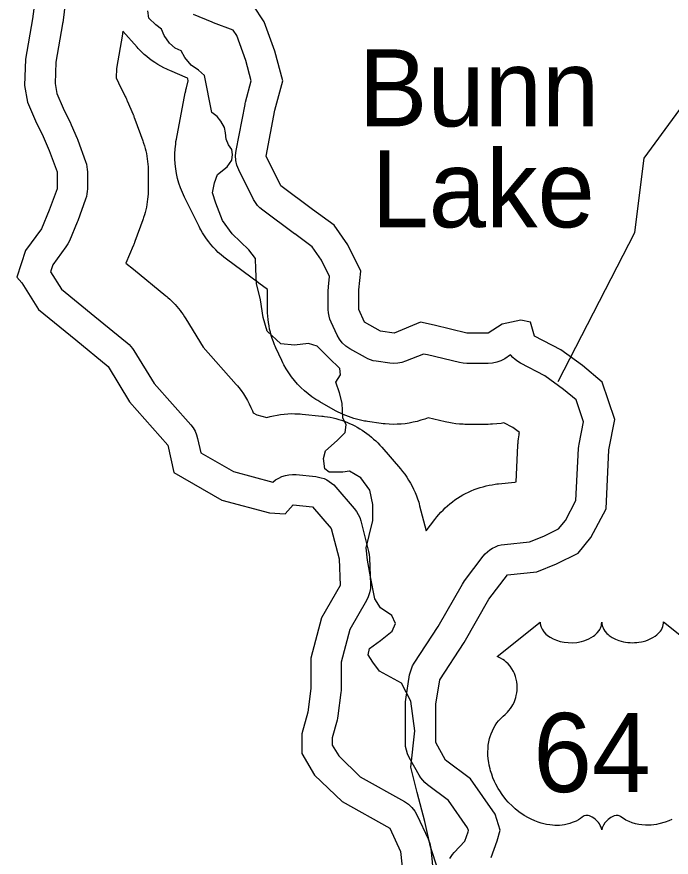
# Model space of a CAD drawing. Extents: x 2126262 to 2293712, y 749403 to 919119.
# Drawn here: x 2213752 to 2215366, y 768873 to 770944 of the extents above; entities that cross this region are included whole.
import ezdxf

# ---------------------------------------------------------------- set-up
doc = ezdxf.new("R2010")
doc.units = 0
for name, color, linetype in [('Exist Boundary Political CountyLine', 7, 'Continuous'), ('Exist Hydrographic Buffer Line', 7, 'Continuous'), ('Exist Hydrographic Lake Shore', 7, 'Continuous'), ('Exist Hydrographic Lake Shore Label', 7, 'Continuous'), ('Exist Hydrographic Misc Water Feature', 7, 'Continuous'), ('Exist Road Primary US Shield CELL', 7, 'Continuous'), ('Exist Road Primary US Shield Number Label', 7, 'Continuous')]:
    doc.layers.add(name, color=color, linetype=linetype)

msp = doc.modelspace()

# ---------------------------------------------------------------- linework, layer by layer
at = {"layer": 'Exist Boundary Political CountyLine'}
msp.add_lwpolyline([(2214790.3, 768843.6), (2214772, 768898.4), (2214757.8, 768961.4), (2214739.5, 769032.4), (2214723.3, 769095.3), (2214733.5, 769184.7), (2214723.3, 769257.8), (2214701, 769302.4), (2214646.2, 769331.9), (2214629.9, 769354.2), (2214618.7, 769372), (2214621.8, 769387.2), (2214649.2, 769407.5), (2214677.6, 769429.8), (2214685.7, 769449.1), (2214676.6, 769468.4), (2214649.2, 769487.7), (2214635, 769510), (2214623.8, 769563.8), (2214616.7, 769605.4), (2214613.7, 769635.9), (2214620.8, 769666.3), (2214629.9, 769702.9), (2214629.9, 769742.5), (2214622.8, 769777.5), (2214600.5, 769807.9), (2214572.1, 769824.2), (2214555.8, 769822.1), (2214522.3, 769822.1), (2214511.2, 769830.3), (2214508.1, 769855.6), (2214513.2, 769874.9), (2214541.6, 769900.3), (2214561.9, 769919.6), (2214563.9, 769938.9), (2214555.8, 769956.1), (2214554.5, 769992), (2214547.5, 770017.1), (2214538.9, 770044), (2214550.1, 770062.2), (2214548.4, 770077.8), (2214521.5, 770103.8), (2214509.4, 770115.9), (2214492.9, 770132.4), (2214471.3, 770139.3), (2214436.6, 770135), (2214402.8, 770138.4), (2214369, 770169.6), (2214359.5, 770203.4), (2214352.5, 770246.8), (2214343, 770286.7), (2214341.3, 770322.2), (2214340.4, 770348.2), (2214323.9, 770369.9), (2214283.2, 770409.3), (2214258.9, 770442.2), (2214242.4, 770484.7), (2214234.6, 770510.7), (2214239.8, 770535), (2214246.8, 770555.8), (2214271, 770574.8), (2214282.3, 770590.9), (2214283.6, 770605), (2214282.3, 770617.5), (2214274.1, 770628.4), (2214268, 770642.7), (2214266.7, 770658.3), (2214264.5, 770671.3), (2214255, 770686.9), (2214246.3, 770698.8), (2214233, 770708.5), (2214215, 770799.1), (2214200, 770812.6), (2214182.2, 770824.7), (2214166.6, 770843.8), (2214157.1, 770860.2), (2214142.8, 770867.2), (2214128.5, 770879.3), (2214115.5, 770898.4), (2214108.5, 770913.5), (2214095.1, 770924.4), (2214077.8, 770940.8), (2214075.2, 770958.6)], dxfattribs=at)
at = {"layer": 'Exist Hydrographic Buffer Line'}
for points in [[(2213874.6, 771004.6), (2213865, 770929.6), (2213864.7, 770928.1), (2213864.5, 770926.6), (2213848.4, 770832.2), (2213846.5, 770779.8), (2213850.9, 770754.8), (2213866, 770718.9), (2213884.3, 770682.3), (2213885.2, 770680.3), (2213886.1, 770678.3), (2213900.6, 770644.5), (2213901.5, 770642.5), (2213902.2, 770640.5), (2213921.6, 770587.3), (2213923.5, 770581.1), (2213924.9, 770574.7), (2213925.8, 770568.2), (2213926.1, 770561.7), (2213926.1, 770520.5), (2213925.8, 770514), (2213924.9, 770507.5), (2213923.5, 770501.1), (2213921.6, 770494.9), (2213902.2, 770441.7), (2213901.5, 770439.9), (2213900.8, 770438.2), (2213881.5, 770392.2), (2213877.7, 770384.5), (2213873, 770377.2), (2213841.1, 770333.3), (2213835.2, 770315.7), (2213862, 770273.2), (2213944.5, 770205.9), (2213944.5, 770205.9), (2213944.5, 770205.9), (2214024.4, 770140.5), (2214029.1, 770136.3), (2214033.5, 770131.8), (2214037.4, 770126.8), (2214040.9, 770121.6), (2214090.7, 770040.1), (2214180.7, 769938.6), (2214186.6, 769931), (2214191.5, 769922.7), (2214195.3, 769913.9), (2214197.9, 769904.6), (2214205.4, 769869.6), (2214286.4, 769823.3), (2214383.3, 769797.3), (2214383.3, 769797.3), (2214390.2, 769802.8), (2214397.8, 769807.4), (2214405.8, 769811.1), (2214414.2, 769813.8), (2214422.9, 769815.6), (2214431.7, 769816.2), (2214440.6, 769815.9), (2214489, 769811), (2214496, 769810), (2214502.9, 769808.3), (2214509.6, 769806), (2214516.1, 769803), (2214522.2, 769799.4), (2214528, 769795.3), (2214533.4, 769790.6), (2214538.3, 769785.4), (2214584.2, 769732.2), (2214589.5, 769725.4), (2214593.9, 769718), (2214597.5, 769710.1), (2214600.1, 769701.9), (2214619.5, 769626.9), (2214621.1, 769619), (2214621.8, 769610.9), (2214624.2, 769545.6), (2214623.9, 769535.1), (2214622.1, 769524.8), (2214618.8, 769514.8), (2214614.3, 769505.4), (2214573.2, 769434), (2214551.7, 769353.8), (2214551.7, 769288.7), (2214551.5, 769284), (2214551.1, 769279.4), (2214543.8, 769221.3), (2214543, 769216.1), (2214541.8, 769210.9), (2214529.9, 769167.3), (2214529.9, 769149.5), (2214545.7, 769122.7), (2214599.1, 769071.2), (2214708, 769010.6), (2214717.8, 769004), (2214726.5, 768996), (2214733.9, 768986.7), (2214739.7, 768976.3), (2214766.3, 768918.2), (2214770.4, 768906.9), (2214772.7, 768895), (2214779.9, 768827.2)], [(2214819.8, 768869.7), (2214823.1, 768875.1), (2214826.8, 768880.2), (2214830.9, 768885), (2214856.5, 768912.3), (2214864.8, 768936), (2214865.6, 768938.8), (2214863.5, 768945.6), (2214816.5, 769013.2), (2214764.6, 769051.9), (2214758.5, 769057), (2214753, 769062.7), (2214748.1, 769068.9), (2214743.9, 769075.6), (2214719.7, 769119.2), (2214715.6, 769127.8), (2214712.6, 769136.8), (2214710.8, 769146.1), (2214710.2, 769155.6), (2214710.2, 769250), (2214710.5, 769255.9), (2214711.2, 769261.8), (2214720.8, 769322.3), (2214722.5, 769330.1), (2214725, 769337.6), (2214728.2, 769344.9), (2214732.2, 769351.7), (2214791.4, 769441.6), (2214850.7, 769546), (2214853.3, 769550.2), (2214856.2, 769554.3), (2214902.2, 769614.8), (2214907.1, 769620.7), (2214912.7, 769626), (2214918.7, 769630.8), (2214925.3, 769634.9), (2214932.2, 769638.3), (2214939.4, 769641), (2214946.8, 769642.9), (2214954.4, 769644.1), (2215016.5, 769650.3), (2215052.1, 769664.5), (2215088.1, 769682.5), (2215104.8, 769703.1), (2215131, 769752.1), (2215137.5, 769880.5), (2215137.9, 769885.8), (2215138.7, 769891), (2215149.5, 769946.4), (2215131.1, 770000), (2215100.6, 770025.9), (2215054.2, 770059.7), (2214993.9, 770090.9), (2214987.3, 770094.8), (2214981.2, 770099.3), (2214975.5, 770104.4), (2214970.4, 770110), (2214969.7, 770111), (2214955.3, 770101.7), (2214945.9, 770096.6), (2214935.8, 770092.8), (2214925.4, 770090.5), (2214914.7, 770089.8), (2214861.5, 770089.8), (2214852.6, 770090.3), (2214843.8, 770091.9), (2214764.9, 770111), (2214754.6, 770113.2), (2214710.7, 770095.3), (2214701.3, 770092.2), (2214691.5, 770090.3), (2214681.6, 770089.8), (2214671.8, 770090.5), (2214637.9, 770095.4), (2214631.1, 770096.7), (2214624.4, 770098.6), (2214617.9, 770101.1), (2214611.7, 770104.2), (2214573, 770126), (2214563.3, 770132.6), (2214554.7, 770140.5), (2214547.4, 770149.7), (2214541.7, 770160), (2214527.2, 770191.4), (2214524.2, 770199), (2214522, 770206.8), (2214520.7, 770214.8), (2214520.2, 770222.9), (2214520.2, 770271.3), (2214520.4, 770275.2), (2214520.7, 770279.1), (2214523.3, 770303.9), (2214503.7, 770344.6), (2214480.5, 770377.7), (2214437.4, 770409), (2214437.2, 770409.2), (2214437, 770409.4), (2214358.3, 770467.5), (2214351.5, 770473.1), (2214345.4, 770479.5), (2214340.2, 770486.6), (2214335.8, 770494.2), (2214299.5, 770566.8), (2214294.9, 770578.2), (2214292.3, 770590.1), (2214291.6, 770602.3), (2214292.9, 770614.5), (2214314.7, 770728.2), (2214315.2, 770730.9), (2214315.9, 770733.5), (2214330.1, 770786.7), (2214316.7, 770836.7), (2214294.2, 770898.2), (2214285.7, 770911.3), (2214236.7, 770929.3), (2214235, 770929.9), (2214233.4, 770930.6), (2214187.4, 770949.9)]]:
    msp.add_lwpolyline(points, dxfattribs=at)
msp.add_lwpolyline([(2214761.3, 769677.4), (2214782.8, 769705.6), (2214785.1, 769708.6), (2214787.6, 769711.6), (2214792.5, 769717.5), (2214797.6, 769723.2), (2214803.1, 769728.7), (2214808.6, 769734), (2214814.3, 769739.2), (2214820.2, 769744.1), (2214826.3, 769748.9), (2214832.5, 769753.5), (2214838.9, 769757.7), (2214845.4, 769761.8), (2214852, 769765.8), (2214858.8, 769769.4), (2214865.7, 769772.8), (2214872.7, 769776), (2214879.8, 769778.9), (2214887, 769781.6), (2214894.3, 769784.1), (2214901.7, 769786.2), (2214909.2, 769788.1), (2214916.7, 769789.8), (2214924.3, 769791.2), (2214931.9, 769792.4), (2214935.7, 769792.9), (2214939.5, 769793.3), (2214980.5, 769797.4), (2214983.2, 769798.5), (2214987.6, 769888), (2214987.8, 769890.7), (2214988, 769893.3), (2214988.5, 769898.6), (2214989, 769903.8), (2214989.7, 769909.1), (2214990.6, 769914.3), (2214991, 769916.9), (2214991.5, 769919.5), (2214991.5, 769919.8), (2214975.2, 769931.7), (2214953, 769943.2), (2214946.7, 769942.1), (2214936.1, 769940.9), (2214925.4, 769940.2), (2214920.1, 769939.9), (2214914.7, 769939.8), (2214861.5, 769939.8), (2214857, 769939.8), (2214852.5, 769940), (2214843.6, 769940.6), (2214834.8, 769941.4), (2214825.9, 769942.7), (2214817.2, 769944.3), (2214812.8, 769945.1), (2214808.4, 769946.1), (2214766.8, 769956.2), (2214762.6, 769954.6), (2214758, 769953), (2214748.6, 769949.8), (2214739.1, 769947), (2214729.4, 769944.9), (2214719.7, 769943), (2214709.9, 769941.5), (2214700, 769940.6), (2214690.1, 769940), (2214680.2, 769939.8), (2214670.3, 769940.2), (2214660.4, 769941), (2214655.5, 769941.4), (2214650.6, 769942), (2214616.7, 769946.9), (2214613.2, 769947.4), (2214609.8, 769948), (2214603, 769949.3), (2214596.2, 769950.8), (2214589.5, 769952.5), (2214582.8, 769954.5), (2214576.2, 769956.5), (2214569.7, 769958.9), (2214563.2, 769961.5), (2214556.8, 769964.1), (2214550.5, 769967.1), (2214544.3, 769970.2), (2214541.2, 769971.8), (2214538.2, 769973.5), (2214499.5, 769995.3), (2214494.4, 769998.3), (2214489.5, 770001.4), (2214479.7, 770008), (2214470.2, 770014.9), (2214461.3, 770022.5), (2214452.7, 770030.5), (2214444.4, 770038.8), (2214436.8, 770047.7), (2214429.6, 770056.9), (2214422.7, 770066.4), (2214416.5, 770076.4), (2214410.8, 770086.7), (2214408, 770091.8), (2214405.5, 770097.1), (2214391, 770128.6), (2214389.3, 770132.3), (2214387.8, 770136), (2214384.8, 770143.5), (2214382, 770151.2), (2214379.6, 770158.9), (2214377.4, 770166.7), (2214375.5, 770174.6), (2214374, 770182.6), (2214372.7, 770190.5), (2214371.6, 770198.6), (2214370.9, 770206.7), (2214370.5, 770214.8), (2214370.3, 770218.8), (2214370.2, 770222.9), (2214370.2, 770271.3), (2214370.3, 770272.4), (2214349.2, 770287.7), (2214349.1, 770287.8), (2214348.9, 770287.9), (2214348.7, 770288.1), (2214348.5, 770288.2), (2214348.3, 770288.4), (2214348.1, 770288.5), (2214348, 770288.6), (2214347.8, 770288.7), (2214269.2, 770346.8), (2214265.7, 770349.5), (2214262.2, 770352.2), (2214255.5, 770357.9), (2214248.9, 770363.7), (2214242.6, 770370), (2214236.5, 770376.4), (2214230.6, 770383), (2214225.2, 770389.9), (2214219.9, 770397), (2214214.8, 770404.2), (2214210.2, 770411.7), (2214205.8, 770419.4), (2214203.6, 770423.2), (2214201.6, 770427.2), (2214165.3, 770499.8), (2214162.7, 770505.3), (2214160.3, 770510.9), (2214155.7, 770522.3), (2214151.6, 770533.8), (2214148.5, 770545.6), (2214145.8, 770557.6), (2214143.7, 770569.6), (2214142.5, 770581.8), (2214141.8, 770594), (2214141.6, 770606.2), (2214142.4, 770618.4), (2214143.8, 770630.6), (2214144.5, 770636.7), (2214145.6, 770642.7), (2214167.3, 770756.4), (2214167.6, 770757.8), (2214167.9, 770759.1), (2214168.4, 770761.7), (2214169, 770764.3), (2214169.6, 770766.9), (2214170.3, 770769.5), (2214170.6, 770770.8), (2214170.9, 770772.1), (2214174.8, 770786.7), (2214173.6, 770791.5), (2214172.9, 770793.3), (2214129.2, 770811.7), (2214125.4, 770813.4), (2214121.6, 770815.1), (2214114.2, 770818.8), (2214106.8, 770822.6), (2214099.7, 770826.8), (2214092.7, 770831.3), (2214085.8, 770835.9), (2214079.2, 770840.9), (2214072.7, 770846.1), (2214066.4, 770851.4), (2214060.4, 770857.1), (2214054.5, 770863), (2214051.6, 770866), (2214048.8, 770869), (2214013.5, 770908.5), (2214013.3, 770907.4), (2214013.1, 770905.9), (2214012.9, 770904.4), (2214012.6, 770902.8), (2214012.5, 770902.1), (2214012.4, 770901.3), (2213997.9, 770816.8), (2213997.1, 770794.1), (2214002.4, 770781.6), (2214018.4, 770749.4), (2214018.9, 770748.4), (2214019.4, 770747.4), (2214020.4, 770745.5), (2214021.3, 770743.5), (2214022.2, 770741.5), (2214023.1, 770739.4), (2214023.6, 770738.4), (2214024, 770737.4), (2214038.5, 770703.5), (2214038.9, 770702.6), (2214039.3, 770701.6), (2214040.1, 770699.7), (2214040.9, 770697.7), (2214041.7, 770695.7), (2214042.4, 770693.8), (2214042.8, 770692.8), (2214043.2, 770691.8), (2214062.5, 770638.6), (2214063.6, 770635.5), (2214064.6, 770632.4), (2214066.6, 770626.1), (2214068.4, 770619.9), (2214070, 770613.5), (2214071.4, 770607.1), (2214072.7, 770600.7), (2214073.7, 770594.2), (2214074.5, 770587.8), (2214075.2, 770581.3), (2214075.6, 770574.7), (2214075.9, 770568.2), (2214076, 770564.9), (2214076.1, 770561.7), (2214076.1, 770520.5), (2214076, 770517.3), (2214075.9, 770514), (2214075.6, 770507.5), (2214075.2, 770500.9), (2214074.5, 770494.4), (2214073.7, 770488), (2214072.7, 770481.5), (2214071.4, 770475.1), (2214070, 770468.7), (2214068.4, 770462.3), (2214066.6, 770456.1), (2214064.6, 770449.8), (2214063.6, 770446.7), (2214062.5, 770443.6), (2214043.2, 770390.4), (2214042.8, 770389.5), (2214042.5, 770388.6), (2214041.9, 770386.9), (2214041.2, 770385.2), (2214040.5, 770383.4), (2214039.8, 770381.7), (2214039.4, 770380.8), (2214039.1, 770380), (2214021, 770337.1), (2214039.3, 770322.2), (2214039.3, 770322.2), (2214039.3, 770322.1), (2214039.4, 770322.1), (2214039.4, 770322.1), (2214039.5, 770322), (2214039.5, 770322), (2214039.5, 770322), (2214039.5, 770322), (2214119.4, 770256.6), (2214121.8, 770254.6), (2214124.2, 770252.5), (2214128.9, 770248.3), (2214133.5, 770244), (2214138, 770239.6), (2214142.3, 770235), (2214146.5, 770230.3), (2214150.6, 770225.5), (2214154.5, 770220.5), (2214158.4, 770215.5), (2214162, 770210.4), (2214165.5, 770205.1), (2214167.2, 770202.5), (2214168.9, 770199.8), (2214211.8, 770129.7), (2214292.9, 770038.1), (2214296.1, 770034.5), (2214299.1, 770030.7), (2214305, 770023.1), (2214310.7, 770015.3), (2214315.8, 770007.2), (2214320.7, 769998.9), (2214325.3, 769990.4), (2214329.4, 769981.7), (2214333.2, 769972.8), (2214334.9, 769968.3), (2214344, 769963.2), (2214368.3, 769956.6), (2214376.5, 769959), (2214385.1, 769961), (2214393.8, 769962.7), (2214402.5, 769964.2), (2214411.3, 769965.1), (2214420.1, 769965.8), (2214429, 769966.2), (2214437.8, 769966.1), (2214446.7, 769965.8), (2214451.1, 769965.5), (2214455.5, 769965.1), (2214503.9, 769960.3), (2214507.4, 769959.9), (2214511, 769959.4), (2214518, 769958.4), (2214525, 769957.2), (2214531.9, 769955.6), (2214538.8, 769953.9), (2214545.7, 769952.1), (2214552.5, 769949.9), (2214559.2, 769947.5), (2214565.8, 769945), (2214572.4, 769942.2), (2214578.8, 769939.2), (2214585.2, 769936.1), (2214591.4, 769932.7), (2214597.6, 769929.1), (2214603.7, 769925.4), (2214609.5, 769921.4), (2214615.3, 769917.2), (2214621, 769913), (2214626.5, 769908.4), (2214631.8, 769903.7), (2214637.1, 769899), (2214642.1, 769893.9), (2214647, 769888.8), (2214649.4, 769886.1), (2214651.8, 769883.5), (2214697.8, 769830.2), (2214700.5, 769826.9), (2214703.2, 769823.6), (2214708.5, 769816.7), (2214713.5, 769809.7), (2214718.2, 769802.5), (2214722.6, 769795.1), (2214726.8, 769787.6), (2214730.6, 769779.8), (2214734.1, 769772), (2214737.5, 769764), (2214740.3, 769755.9), (2214743, 769747.7), (2214744.2, 769743.6), (2214745.3, 769739.4)], close=True, dxfattribs=at)
at = {"layer": 'Exist Hydrographic Lake Shore'}
for points in [[(2213800.3, 771014.2), (2213790.6, 770939.2), (2213773.6, 770840), (2213771.2, 770774.6), (2213778.5, 770733.5), (2213797.8, 770687.5), (2213817.2, 770648.8), (2213831.7, 770614.9), (2213851.1, 770561.7), (2213851.1, 770520.5), (2213831.7, 770467.3), (2213812.4, 770421.3), (2213773.6, 770368.1), (2213751.9, 770302.7), (2213764, 770288.2), (2213805.1, 770222.9), (2213897.1, 770147.8), (2213976.9, 770082.5), (2214030.2, 769995.4), (2214124.5, 769888.9), (2214139.1, 769821.1), (2214257.6, 769753.4), (2214375, 769721.9), (2214413.7, 769719.5), (2214433.1, 769741.3), (2214481.5, 769736.4), (2214527.5, 769683.2), (2214546.8, 769608.2), (2214549.3, 769542.8), (2214503.3, 769463), (2214476.7, 769363.7), (2214476.7, 769288.7), (2214469.4, 769230.6), (2214454.9, 769177.4), (2214454.9, 769129), (2214486.3, 769075.7), (2214554.1, 769010.4), (2214671.5, 768945.1), (2214698.1, 768887), (2214705.4, 768819.2)], [(2214922, 768872.5), (2214936.5, 768913.6), (2214943.7, 768940.2), (2214931.6, 768978.9), (2214871.1, 769066.1), (2214809.4, 769112), (2214785.2, 769155.6), (2214785.2, 769250), (2214794.9, 769310.5), (2214855.4, 769402.5), (2214915.9, 769508.9), (2214961.9, 769569.4), (2215034.5, 769576.7), (2215082.9, 769596.1), (2215136.1, 769622.7), (2215167.6, 769661.4), (2215205.1, 769731.6), (2215212.4, 769876.8), (2215226.9, 769951.8), (2215195.4, 770043.8), (2215147, 770084.9), (2215093.8, 770123.6), (2215028.4, 770157.5), (2215018.8, 770191.4), (2214994.6, 770196.2), (2214948.6, 770186.6), (2214914.7, 770164.8), (2214861.5, 770164.8), (2214781.6, 770184.1), (2214747.7, 770191.4), (2214682.4, 770164.8), (2214648.5, 770169.6), (2214609.8, 770191.4), (2214595.2, 770222.9), (2214595.2, 770271.3), (2214600.1, 770317.2), (2214568.6, 770382.6), (2214534.7, 770431), (2214481.5, 770469.7), (2214402.9, 770527.8), (2214366.6, 770600.4), (2214388.3, 770714.1), (2214407.7, 770786.7), (2214388.3, 770859.3), (2214361.7, 770931.9), (2214335.1, 770973.1)]]:
    msp.add_lwpolyline(points, dxfattribs=at)
at = {"layer": 'Exist Hydrographic Misc Water Feature'}
msp.add_lwpolyline([(2215086.9, 770045.6), (2215275.8, 770412.4), (2215298.9, 770595.6), (2215587.8, 770989.8), (2215885.8, 771367.6), (2215983.8, 771542.6)], dxfattribs=at)
at = {"layer": 'Exist Road Primary US Shield CELL'}
msp.add_lwpolyline([(2215367.7, 768966.2), (2215360.4, 768963.1), (2215351, 768959.5), (2215335.3, 768955.2), (2215329.6, 768954), (2215322.8, 768953), (2215316.5, 768952.4), (2215310.4, 768952), (2215302.1, 768952), (2215293.8, 768952.6), (2215286.1, 768953.7), (2215278, 768955.4), (2215269.5, 768957.9), (2215261.8, 768961), (2215254, 768964.8), (2215240.9, 768973.1), (2215237.1, 768975.1), (2215234.9, 768975.7), (2215229.9, 768975.9), (2215225.1, 768974.9), (2215220.2, 768973), (2215217.2, 768971.4), (2215213.3, 768968.8), (2215210.3, 768966.4), (2215206.7, 768963), (2215204.2, 768960.1), (2215202.2, 768957.8), (2215198.5, 768952), (2215197.2, 768949.2), (2215195.8, 768945.6), (2215194.6, 768940.4), (2215193, 768947), (2215191, 768951.4), (2215188.7, 768955.2), (2215186.4, 768958.5), (2215182.7, 768962.8), (2215179.4, 768966), (2215175.3, 768969.2), (2215171.1, 768971.8), (2215167.7, 768973.6), (2215164.5, 768974.8), (2215160.7, 768975.7), (2215157.6, 768976), (2215155, 768975.9), (2215151.4, 768975.1), (2215146.6, 768971.6), (2215142.1, 768968.5), (2215137.1, 768965.4), (2215131.2, 768962.3), (2215126.9, 768960.3), (2215121.7, 768958.3), (2215115.7, 768956.2), (2215109.2, 768954.6), (2215102.5, 768953.2), (2215096.6, 768952.3), (2215090.2, 768951.7), (2215084.5, 768951.5), (2215078.6, 768951.6), (2215073, 768952), (2215066.5, 768952.6), (2215058.5, 768953.8), (2215051.8, 768955.3), (2215044.8, 768957.2), (2215037.6, 768959.5), (2215029.9, 768962.4), (2215020.2, 768966.6), (2215013.5, 768970.1), (2215002.9, 768976.2), (2214990.4, 768984.8), (2214981.1, 768992.4), (2214974.2, 768998.6), (2214964.1, 769008.9), (2214958.1, 769015.6), (2214948.8, 769027.7), (2214942.9, 769036.4), (2214939, 769042.8), (2214933.4, 769053.1), (2214930.2, 769059.6), (2214926.2, 769069), (2214923.1, 769077.6), (2214920.4, 769085.7), (2214919, 769091), (2214917, 769100.1), (2214915.8, 769106.5), (2214914.6, 769115.4), (2214913.9, 769124.7), (2214913.8, 769133.3), (2214914, 769140.5), (2214914.8, 769148.9), (2214916.2, 769157.7), (2214917.9, 769165.3), (2214919.5, 769170.8), (2214921.7, 769177.4), (2214924.7, 769184.8), (2214928.2, 769191.8), (2214931.6, 769197.6), (2214935.8, 769203.9), (2214939.9, 769209.3), (2214945.4, 769215.2), (2214951, 769220.6), (2214956.2, 769224.8), (2214962.4, 769230.8), (2214965.6, 769234.4), (2214969.4, 769239.5), (2214972.5, 769244.2), (2214974.9, 769248.5), (2214978.2, 769254.7), (2214980.1, 769259.3), (2214982.6, 769266.5), (2214983.8, 769271.5), (2214985, 769278), (2214985.9, 769284.1), (2214986.2, 769291.7), (2214986, 769297.9), (2214985.2, 769305.3), (2214983.8, 769312.3), (2214982.1, 769318.5), (2214979.5, 769325.5), (2214977.1, 769330.7), (2214973, 769337.6), (2214968.5, 769344.1), (2214963.8, 769349.4), (2214959.1, 769354.1), (2214954.6, 769357.6), (2214950.3, 769360.7), (2214944.9, 769363.9), (2214939.7, 769366.5), (2214936.4, 769367.8), (2215042.7, 769452.5), (2215042.9, 769448.1), (2215044, 769442.9), (2215044.8, 769440.2), (2215047.3, 769435), (2215051.3, 769428.9), (2215056.9, 769423), (2215063.2, 769417.8), (2215067.5, 769415), (2215074.8, 769411.1), (2215083, 769407.7), (2215092.1, 769405), (2215101.5, 769403.1), (2215111.7, 769402), (2215121.8, 769401.8), (2215132.8, 769402.6), (2215144.8, 769405), (2215150.4, 769406.4), (2215156.6, 769408.5), (2215162.4, 769410.9), (2215168.7, 769414.3), (2215173.8, 769417.6), (2215177.8, 769420.5), (2215183.4, 769425.9), (2215187.9, 769431.5), (2215189.8, 769434.6), (2215191.4, 769437.6), (2215193.7, 769444), (2215194.3, 769446.8), (2215194.7, 769452.7), (2215195.1, 769447.8), (2215195.6, 769444.7), (2215196.4, 769441.7), (2215197.7, 769438.5), (2215199.9, 769434), (2215202.5, 769430.2), (2215207.2, 769424.6), (2215210.1, 769421.8), (2215212.8, 769419.6), (2215220.1, 769414.7), (2215228.5, 769410.4), (2215232.6, 769408.6), (2215236.9, 769407.1), (2215242.3, 769405.5), (2215247.9, 769404.1), (2215253.4, 769403.2), (2215259.1, 769402.4), (2215264.8, 769401.9), (2215269.6, 769401.8), (2215275.3, 769401.9), (2215280.7, 769402.2), (2215286.1, 769402.8), (2215292.2, 769403.8), (2215297, 769404.9), (2215303.4, 769406.6), (2215309.2, 769408.7), (2215314.2, 769410.9), (2215320.8, 769414.3), (2215326.2, 769417.6), (2215330.1, 769420.8), (2215334.7, 769425), (2215339.1, 769430.1), (2215341.7, 769433.8), (2215343.5, 769437.7), (2215345.2, 769441.7), (2215346.2, 769446), (2215346.7, 769449.7), (2215346.8, 769452.8), (2215453.1, 769368.2)], dxfattribs=at)

# ---------------------------------------------------------------- texts
at = {"layer": 'Exist Hydrographic Lake Shore Label'}
for s, p in [('Bunn', (2214595, 770674.1)), ('Lake', (2214626.5, 770425.4))]:
    msp.add_text(s, height=190, dxfattribs=at).set_placement(p)
at = {"layer": 'Exist Road Primary US Shield Number Label'}
msp.add_text('64', height=195, dxfattribs=at).set_placement((2215025.5, 769033.7))

doc.saveas('drawing.dxf')
